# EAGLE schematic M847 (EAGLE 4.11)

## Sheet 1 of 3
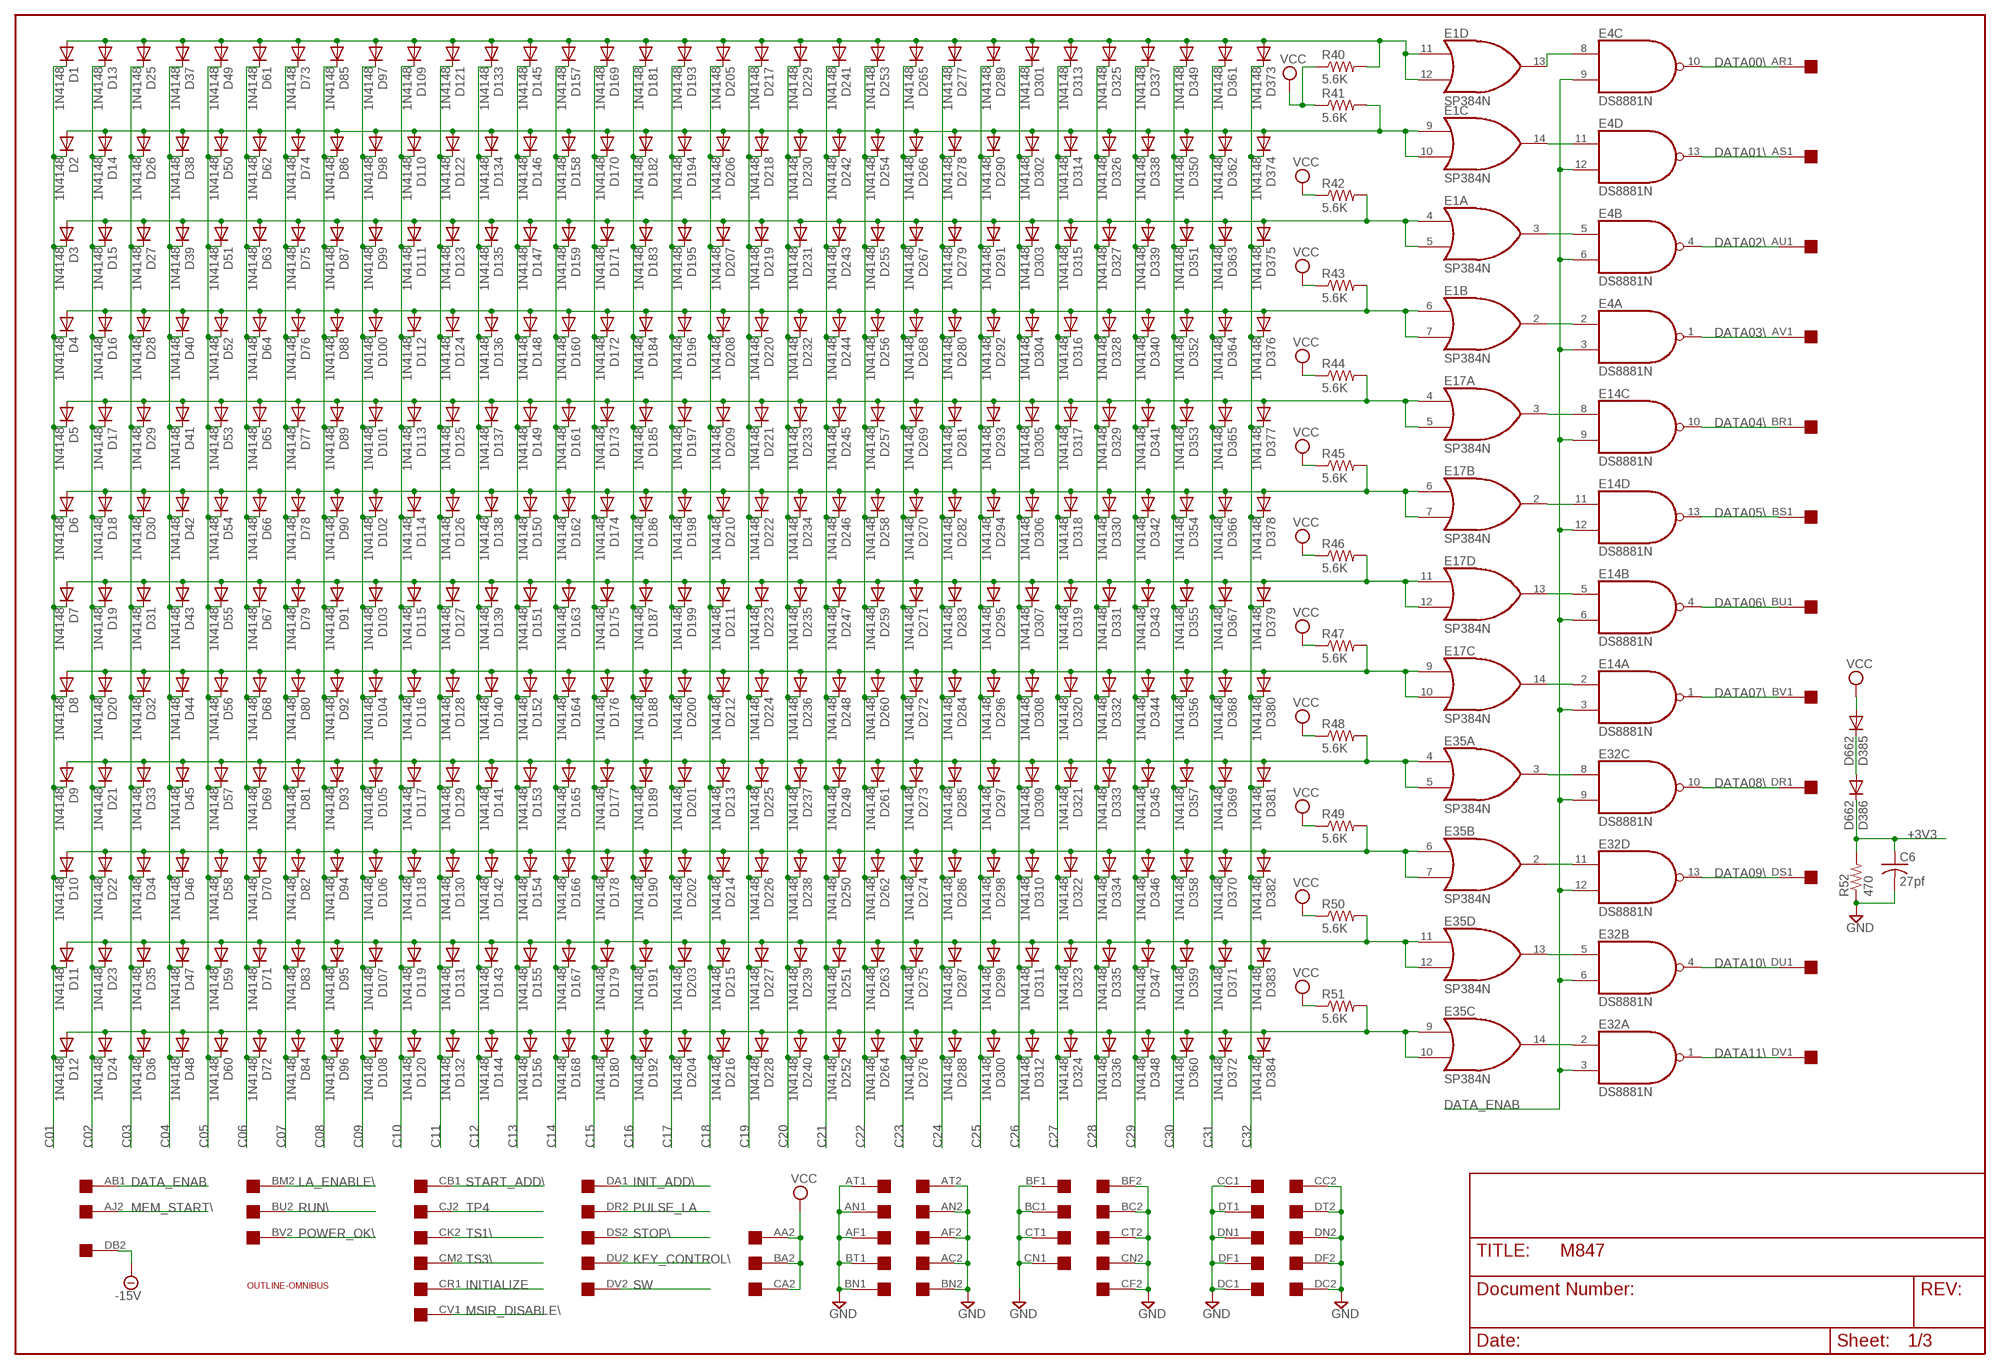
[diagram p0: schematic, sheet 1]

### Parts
C6  27pf  C-US050-025X075  [C050-025X075]
D1  1N4148  [DO35-10]
D2  1N4148  [DO35-10]
D3  1N4148  [DO35-10]
D4  1N4148  [DO35-10]
D5  1N4148  [DO35-10]
D6  1N4148  [DO35-10]
D7  1N4148  [DO35-10]
D8  1N4148  [DO35-10]
D9  1N4148  [DO35-10]
D10  1N4148  [DO35-10]
D11  1N4148  [DO35-10]
D12  1N4148  [DO35-10]
D13  1N4148  [DO35-10]
D14  1N4148  [DO35-10]
D15  1N4148  [DO35-10]
D16  1N4148  [DO35-10]
D17  1N4148  [DO35-10]
D18  1N4148  [DO35-10]
D19  1N4148  [DO35-10]
D20  1N4148  [DO35-10]
D21  1N4148  [DO35-10]
D22  1N4148  [DO35-10]
D23  1N4148  [DO35-10]
D24  1N4148  [DO35-10]
D25  1N4148  [DO35-10]
D26  1N4148  [DO35-10]
D27  1N4148  [DO35-10]
D28  1N4148  [DO35-10]
D29  1N4148  [DO35-10]
D30  1N4148  [DO35-10]
D31  1N4148  [DO35-10]
D32  1N4148  [DO35-10]
D33  1N4148  [DO35-10]
D34  1N4148  [DO35-10]
D35  1N4148  [DO35-10]
D36  1N4148  [DO35-10]
D37  1N4148  [DO35-10]
D38  1N4148  [DO35-10]
D39  1N4148  [DO35-10]
D40  1N4148  [DO35-10]
D41  1N4148  [DO35-10]
D42  1N4148  [DO35-10]
D43  1N4148  [DO35-10]
D44  1N4148  [DO35-10]
D45  1N4148  [DO35-10]
D46  1N4148  [DO35-10]
D47  1N4148  [DO35-10]
D48  1N4148  [DO35-10]
D49  1N4148  [DO35-10]
D50  1N4148  [DO35-10]
D51  1N4148  [DO35-10]
D52  1N4148  [DO35-10]
D53  1N4148  [DO35-10]
D54  1N4148  [DO35-10]
D55  1N4148  [DO35-10]
D56  1N4148  [DO35-10]
D57  1N4148  [DO35-10]
D58  1N4148  [DO35-10]
D59  1N4148  [DO35-10]
D60  1N4148  [DO35-10]
D61  1N4148  [DO35-10]
D62  1N4148  [DO35-10]
D63  1N4148  [DO35-10]
D64  1N4148  [DO35-10]
D65  1N4148  [DO35-10]
D66  1N4148  [DO35-10]
D67  1N4148  [DO35-10]
D68  1N4148  [DO35-10]
D69  1N4148  [DO35-10]
D70  1N4148  [DO35-10]
D71  1N4148  [DO35-10]
D72  1N4148  [DO35-10]
D73  1N4148  [DO35-10]
D74  1N4148  [DO35-10]
D75  1N4148  [DO35-10]
D76  1N4148  [DO35-10]
D77  1N4148  [DO35-10]
D78  1N4148  [DO35-10]
D79  1N4148  [DO35-10]
D80  1N4148  [DO35-10]
D81  1N4148  [DO35-10]
D82  1N4148  [DO35-10]
D83  1N4148  [DO35-10]
D84  1N4148  [DO35-10]
D85  1N4148  [DO35-10]
D86  1N4148  [DO35-10]
D87  1N4148  [DO35-10]
D88  1N4148  [DO35-10]
D89  1N4148  [DO35-10]
D90  1N4148  [DO35-10]
D91  1N4148  [DO35-10]
D92  1N4148  [DO35-10]
D93  1N4148  [DO35-10]
D94  1N4148  [DO35-10]
D95  1N4148  [DO35-10]
D96  1N4148  [DO35-10]
D97  1N4148  [DO35-10]
D98  1N4148  [DO35-10]
D99  1N4148  [DO35-10]
D100  1N4148  [DO35-10]
D101  1N4148  [DO35-10]
D102  1N4148  [DO35-10]
D103  1N4148  [DO35-10]
D104  1N4148  [DO35-10]
D105  1N4148  [DO35-10]
D106  1N4148  [DO35-10]
D107  1N4148  [DO35-10]
D108  1N4148  [DO35-10]
D109  1N4148  [DO35-10]
D110  1N4148  [DO35-10]
D111  1N4148  [DO35-10]
D112  1N4148  [DO35-10]
D113  1N4148  [DO35-10]
D114  1N4148  [DO35-10]
D115  1N4148  [DO35-10]
D116  1N4148  [DO35-10]
D117  1N4148  [DO35-10]
D118  1N4148  [DO35-10]
D119  1N4148  [DO35-10]
D120  1N4148  [DO35-10]
D121  1N4148  [DO35-10]
D122  1N4148  [DO35-10]
D123  1N4148  [DO35-10]
D124  1N4148  [DO35-10]
D125  1N4148  [DO35-10]
D126  1N4148  [DO35-10]
D127  1N4148  [DO35-10]
D128  1N4148  [DO35-10]
D129  1N4148  [DO35-10]
D130  1N4148  [DO35-10]
D131  1N4148  [DO35-10]
D132  1N4148  [DO35-10]
D133  1N4148  [DO35-10]
D134  1N4148  [DO35-10]
D135  1N4148  [DO35-10]
D136  1N4148  [DO35-10]
D137  1N4148  [DO35-10]
D138  1N4148  [DO35-10]
D139  1N4148  [DO35-10]
D140  1N4148  [DO35-10]
D141  1N4148  [DO35-10]
D142  1N4148  [DO35-10]
D143  1N4148  [DO35-10]
D144  1N4148  [DO35-10]
D145  1N4148  [DO35-10]
D146  1N4148  [DO35-10]
D147  1N4148  [DO35-10]
D148  1N4148  [DO35-10]
D149  1N4148  [DO35-10]
D150  1N4148  [DO35-10]
D151  1N4148  [DO35-10]
D152  1N4148  [DO35-10]
D153  1N4148  [DO35-10]
D154  1N4148  [DO35-10]
D155  1N4148  [DO35-10]
D156  1N4148  [DO35-10]
D157  1N4148  [DO35-10]
D158  1N4148  [DO35-10]
D159  1N4148  [DO35-10]
D160  1N4148  [DO35-10]
D161  1N4148  [DO35-10]
D162  1N4148  [DO35-10]
D163  1N4148  [DO35-10]
D164  1N4148  [DO35-10]
D165  1N4148  [DO35-10]
D166  1N4148  [DO35-10]
D167  1N4148  [DO35-10]
D168  1N4148  [DO35-10]
D169  1N4148  [DO35-10]
D170  1N4148  [DO35-10]
D171  1N4148  [DO35-10]
D172  1N4148  [DO35-10]
D173  1N4148  [DO35-10]
D174  1N4148  [DO35-10]
D175  1N4148  [DO35-10]
D176  1N4148  [DO35-10]
D177  1N4148  [DO35-10]
D178  1N4148  [DO35-10]
D179  1N4148  [DO35-10]
D180  1N4148  [DO35-10]
D181  1N4148  [DO35-10]
D182  1N4148  [DO35-10]
D183  1N4148  [DO35-10]
D184  1N4148  [DO35-10]
D185  1N4148  [DO35-10]
D186  1N4148  [DO35-10]
D187  1N4148  [DO35-10]
D188  1N4148  [DO35-10]
D189  1N4148  [DO35-10]
D190  1N4148  [DO35-10]
D191  1N4148  [DO35-10]
D192  1N4148  [DO35-10]
D193  1N4148  [DO35-10]
D194  1N4148  [DO35-10]
D195  1N4148  [DO35-10]
D196  1N4148  [DO35-10]
D197  1N4148  [DO35-10]
D198  1N4148  [DO35-10]
D199  1N4148  [DO35-10]
D200  1N4148  [DO35-10]
D201  1N4148  [DO35-10]
D202  1N4148  [DO35-10]
D203  1N4148  [DO35-10]
D204  1N4148  [DO35-10]
D205  1N4148  [DO35-10]
D206  1N4148  [DO35-10]
D207  1N4148  [DO35-10]
D208  1N4148  [DO35-10]
D209  1N4148  [DO35-10]
D210  1N4148  [DO35-10]
D211  1N4148  [DO35-10]
D212  1N4148  [DO35-10]
D213  1N4148  [DO35-10]
D214  1N4148  [DO35-10]
D215  1N4148  [DO35-10]
D216  1N4148  [DO35-10]
D217  1N4148  [DO35-10]
D218  1N4148  [DO35-10]
D219  1N4148  [DO35-10]
D220  1N4148  [DO35-10]
D221  1N4148  [DO35-10]
D222  1N4148  [DO35-10]
D223  1N4148  [DO35-10]
D224  1N4148  [DO35-10]
D225  1N4148  [DO35-10]
D226  1N4148  [DO35-10]
D227  1N4148  [DO35-10]
D228  1N4148  [DO35-10]
D229  1N4148  [DO35-10]
D230  1N4148  [DO35-10]
D231  1N4148  [DO35-10]
D232  1N4148  [DO35-10]
D233  1N4148  [DO35-10]
D234  1N4148  [DO35-10]
D235  1N4148  [DO35-10]
D236  1N4148  [DO35-10]
D237  1N4148  [DO35-10]
D238  1N4148  [DO35-10]
D239  1N4148  [DO35-10]
D240  1N4148  [DO35-10]
D241  1N4148  [DO35-10]
D242  1N4148  [DO35-10]
D243  1N4148  [DO35-10]
D244  1N4148  [DO35-10]
D245  1N4148  [DO35-10]
D246  1N4148  [DO35-10]
D247  1N4148  [DO35-10]
D248  1N4148  [DO35-10]
D249  1N4148  [DO35-10]
D250  1N4148  [DO35-10]
D251  1N4148  [DO35-10]
D252  1N4148  [DO35-10]
D253  1N4148  [DO35-10]
D254  1N4148  [DO35-10]
D255  1N4148  [DO35-10]
D256  1N4148  [DO35-10]
D257  1N4148  [DO35-10]
D258  1N4148  [DO35-10]
D259  1N4148  [DO35-10]
D260  1N4148  [DO35-10]
D261  1N4148  [DO35-10]
D262  1N4148  [DO35-10]
D263  1N4148  [DO35-10]
D264  1N4148  [DO35-10]
D265  1N4148  [DO35-10]
D266  1N4148  [DO35-10]
D267  1N4148  [DO35-10]
D268  1N4148  [DO35-10]
D269  1N4148  [DO35-10]
D270  1N4148  [DO35-10]
D271  1N4148  [DO35-10]
D272  1N4148  [DO35-10]
D273  1N4148  [DO35-10]
D274  1N4148  [DO35-10]
D275  1N4148  [DO35-10]
D276  1N4148  [DO35-10]
D277  1N4148  [DO35-10]
D278  1N4148  [DO35-10]
D279  1N4148  [DO35-10]
D280  1N4148  [DO35-10]
D281  1N4148  [DO35-10]
D282  1N4148  [DO35-10]
D283  1N4148  [DO35-10]
D284  1N4148  [DO35-10]
D285  1N4148  [DO35-10]
D286  1N4148  [DO35-10]
D287  1N4148  [DO35-10]
D288  1N4148  [DO35-10]
D289  1N4148  [DO35-10]
D290  1N4148  [DO35-10]
D291  1N4148  [DO35-10]
D292  1N4148  [DO35-10]
D293  1N4148  [DO35-10]
D294  1N4148  [DO35-10]
D295  1N4148  [DO35-10]
D296  1N4148  [DO35-10]
D297  1N4148  [DO35-10]
D298  1N4148  [DO35-10]
D299  1N4148  [DO35-10]
D300  1N4148  [DO35-10]
D301  1N4148  [DO35-10]
D302  1N4148  [DO35-10]
D303  1N4148  [DO35-10]
D304  1N4148  [DO35-10]
D305  1N4148  [DO35-10]
D306  1N4148  [DO35-10]
D307  1N4148  [DO35-10]
D308  1N4148  [DO35-10]
D309  1N4148  [DO35-10]
D310  1N4148  [DO35-10]
D311  1N4148  [DO35-10]
D312  1N4148  [DO35-10]
D313  1N4148  [DO35-10]
D314  1N4148  [DO35-10]
D315  1N4148  [DO35-10]
D316  1N4148  [DO35-10]
D317  1N4148  [DO35-10]
D318  1N4148  [DO35-10]
D319  1N4148  [DO35-10]
D320  1N4148  [DO35-10]
D321  1N4148  [DO35-10]
D322  1N4148  [DO35-10]
D323  1N4148  [DO35-10]
D324  1N4148  [DO35-10]
D325  1N4148  [DO35-10]
D326  1N4148  [DO35-10]
D327  1N4148  [DO35-10]
D328  1N4148  [DO35-10]
D329  1N4148  [DO35-10]
D330  1N4148  [DO35-10]
D331  1N4148  [DO35-10]
D332  1N4148  [DO35-10]
D333  1N4148  [DO35-10]
D334  1N4148  [DO35-10]
D335  1N4148  [DO35-10]
D336  1N4148  [DO35-10]
D337  1N4148  [DO35-10]
D338  1N4148  [DO35-10]
D339  1N4148  [DO35-10]
D340  1N4148  [DO35-10]
D341  1N4148  [DO35-10]
D342  1N4148  [DO35-10]
D343  1N4148  [DO35-10]
D344  1N4148  [DO35-10]
D345  1N4148  [DO35-10]
D346  1N4148  [DO35-10]
D347  1N4148  [DO35-10]
D348  1N4148  [DO35-10]
D349  1N4148  [DO35-10]
D350  1N4148  [DO35-10]
D351  1N4148  [DO35-10]
D352  1N4148  [DO35-10]
D353  1N4148  [DO35-10]
D354  1N4148  [DO35-10]
D355  1N4148  [DO35-10]
D356  1N4148  [DO35-10]
D357  1N4148  [DO35-10]
D358  1N4148  [DO35-10]
D359  1N4148  [DO35-10]
D360  1N4148  [DO35-10]
D361  1N4148  [DO35-10]
D362  1N4148  [DO35-10]
D363  1N4148  [DO35-10]
D364  1N4148  [DO35-10]
D365  1N4148  [DO35-10]
D366  1N4148  [DO35-10]
D367  1N4148  [DO35-10]
D368  1N4148  [DO35-10]
D369  1N4148  [DO35-10]
D370  1N4148  [DO35-10]
D371  1N4148  [DO35-10]
D372  1N4148  [DO35-10]
D373  1N4148  [DO35-10]
D374  1N4148  [DO35-10]
D375  1N4148  [DO35-10]
D376  1N4148  [DO35-10]
D377  1N4148  [DO35-10]
D378  1N4148  [DO35-10]
D379  1N4148  [DO35-10]
D380  1N4148  [DO35-10]
D381  1N4148  [DO35-10]
D382  1N4148  [DO35-10]
D383  1N4148  [DO35-10]
D384  1N4148  [DO35-10]
D385  D662  1N4148  [DO35-10]
D386  D662  1N4148  [DO35-10]
E1  SP384N  [DIL14]
E4  DS8881N  [DIL14]
E14  DS8881N  [DIL14]
E17  SP384N  [DIL14]
E32  DS8881N  [DIL14]
E35  SP384N  [DIL14]
R40  5.6K  R-US_0207/10  [0207/10]
R41  5.6K  R-US_0207/10  [0207/10]
R42  5.6K  R-US_0207/10  [0207/10]
R43  5.6K  R-US_0207/10  [0207/10]
R44  5.6K  R-US_0207/10  [0207/10]
R45  5.6K  R-US_0207/10  [0207/10]
R46  5.6K  R-US_0207/10  [0207/10]
R47  5.6K  R-US_0207/10  [0207/10]
R48  5.6K  R-US_0207/10  [0207/10]
R49  5.6K  R-US_0207/10  [0207/10]
R50  5.6K  R-US_0207/10  [0207/10]
R51  5.6K  R-US_0207/10  [0207/10]
R52  470  R-US_0207/10  [0207/10]
U$1  OUTLINE-OMNIBUS  [OMNIBUS]
U$2  QUAD  [EDGE-CON8]

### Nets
+3V3 [supply]: C6.1 D386.C R52.2 ; also sheet 2,3
-15V [supply]: U$2.DB2 ; also sheet 2,3
C01: D1.C D2.C D3.C D4.C D5.C D6.C D7.C D8.C D9.C D10.C D11.C D12.C ; also sheet 2
C02: D13.C D14.C D15.C D16.C D17.C D18.C D19.C D20.C D21.C D22.C D23.C D24.C ; also sheet 2
C03: D25.C D26.C D27.C D28.C D29.C D30.C D31.C D32.C D33.C D34.C D35.C D36.C ; also sheet 2
C04: D37.C D38.C D39.C D40.C D41.C D42.C D43.C D44.C D45.C D46.C D47.C D48.C ; also sheet 2
C05: D49.C D50.C D51.C D52.C D53.C D54.C D55.C D56.C D57.C D58.C D59.C D60.C ; also sheet 2
C06: D61.C D62.C D63.C D64.C D65.C D66.C D67.C D68.C D69.C D70.C D71.C D72.C ; also sheet 2
C07: D73.C D74.C D75.C D76.C D77.C D78.C D79.C D80.C D81.C D82.C D83.C D84.C ; also sheet 2
C08: D85.C D86.C D87.C D88.C D89.C D90.C D91.C D92.C D93.C D94.C D95.C D96.C ; also sheet 2
C09: D97.C D98.C D99.C D100.C D101.C D102.C D103.C D104.C D105.C D106.C D107.C D108.C ; also sheet 2
C10: D109.C D110.C D111.C D112.C D113.C D114.C D115.C D116.C D117.C D118.C D119.C D120.C ; also sheet 2
C11: D121.C D122.C D123.C D124.C D125.C D126.C D127.C D128.C D129.C D130.C D131.C D132.C ; also sheet 2
C12: D133.C D134.C D135.C D136.C D137.C D138.C D139.C D140.C D141.C D142.C D143.C D144.C ; also sheet 2
C13: D145.C D146.C D147.C D148.C D149.C D150.C D151.C D152.C D153.C D154.C D155.C D156.C ; also sheet 2
C14: D157.C D158.C D159.C D160.C D161.C D162.C D163.C D164.C D165.C D166.C D167.C D168.C ; also sheet 2
C15: D169.C D170.C D171.C D172.C D173.C D174.C D175.C D176.C D177.C D178.C D179.C D180.C ; also sheet 2
C16: D181.C D182.C D183.C D184.C D185.C D186.C D187.C D188.C D189.C D190.C D191.C D192.C ; also sheet 2
C17: D193.C D194.C D195.C D196.C D197.C D198.C D199.C D200.C D201.C D202.C D203.C D204.C ; also sheet 2
C18: D205.C D206.C D207.C D208.C D209.C D210.C D211.C D212.C D213.C D214.C D215.C D216.C ; also sheet 2
C19: D217.C D218.C D219.C D220.C D221.C D222.C D223.C D224.C D225.C D226.C D227.C D228.C ; also sheet 2
C20: D229.C D230.C D231.C D232.C D233.C D234.C D235.C D236.C D237.C D238.C D239.C D240.C ; also sheet 2
C21: D241.C D242.C D243.C D244.C D245.C D246.C D247.C D248.C D249.C D250.C D251.C D252.C ; also sheet 2
C22: D253.C D254.C D255.C D256.C D257.C D258.C D259.C D260.C D261.C D262.C D263.C D264.C ; also sheet 2
C23: D265.C D266.C D267.C D268.C D269.C D270.C D271.C D272.C D273.C D274.C D275.C D276.C ; also sheet 2
C24: D277.C D278.C D279.C D280.C D281.C D282.C D283.C D284.C D285.C D286.C D287.C D288.C ; also sheet 2
C25: D289.C D290.C D291.C D292.C D293.C D294.C D295.C D296.C D297.C D298.C D299.C D300.C ; also sheet 2
C26: D301.C D302.C D303.C D304.C D305.C D306.C D307.C D308.C D309.C D310.C D311.C D312.C ; also sheet 2
C27: D313.C D314.C D315.C D316.C D317.C D318.C D319.C D320.C D321.C D322.C D323.C D324.C ; also sheet 2
C28: D325.C D326.C D327.C D328.C D329.C D330.C D331.C D332.C D333.C D334.C D335.C D336.C ; also sheet 2
C29: D337.C D338.C D339.C D340.C D341.C D342.C D343.C D344.C D345.C D346.C D347.C D348.C ; also sheet 2
C30: D349.C D350.C D351.C D352.C D353.C D354.C D355.C D356.C D357.C D358.C D359.C D360.C ; also sheet 2
C31: D361.C D362.C D363.C D364.C D365.C D366.C D367.C D368.C D369.C D370.C D371.C D372.C ; also sheet 2
C32: D373.C D374.C D375.C D376.C D377.C D378.C D379.C D380.C D381.C D382.C D383.C D384.C ; also sheet 2
DATA00\: E4.10(C:O) U$2.AR1 ; also sheet 2
DATA01\: E4.13(D:O) U$2.AS1 ; also sheet 2
DATA02\: E4.4(B:O) U$2.AU1 ; also sheet 2
DATA03\: E4.1(A:O) U$2.AV1 ; also sheet 2
DATA04\: E14.10(C:O) U$2.BR1 ; also sheet 2
DATA05\: E14.13(D:O) U$2.BS1 ; also sheet 2
DATA06\: E14.4(B:O) U$2.BU1 ; also sheet 2
DATA07\: E14.1(A:O) U$2.BV1 ; also sheet 2
DATA08\: E32.10(C:O) U$2.DR1 ; also sheet 2
DATA09\: E32.13(D:O) U$2.DS1 ; also sheet 2
DATA10\: E32.4(B:O) U$2.DU1 ; also sheet 2
DATA11\: E32.1(A:O) U$2.DV1 ; also sheet 2
DATA_ENAB: E4.3(A:I1) E4.6(B:I1) E4.9(C:I1) E4.12(D:I1) E14.3(A:I1) E14.6(B:I1) E14.9(C:I1) E14.12(D:I1) E32.3(A:I1) E32.6(B:I1) E32.9(C:I1) E32.12(D:I1) U$2.AB1 ; also sheet 3
GND [supply]: C6.2 R52.1 U$2.AC2 U$2.AF1 U$2.AF2 U$2.AN1 U$2.AN2 U$2.AT1 U$2.AT2 U$2.BC1 U$2.BC2 U$2.BF1 U$2.BF2 U$2.BN1 U$2.BN2 U$2.BT1 U$2.CC1 U$2.CC2 U$2.CF2 U$2.CN1 U$2.CN2 U$2.CT1 U$2.CT2 U$2.DC1 U$2.DC2 U$2.DF1 U$2.DF2 U$2.DN1 U$2.DN2 U$2.DT1 U$2.DT2 ; also sheet 2,3
INIT_ADD\: U$2.DA1 ; also sheet 2,3
INITIALIZE: U$2.CR1 ; also sheet 3
KEY_CONTROL\: U$2.DU2 ; also sheet 2
LA_ENABLE\: U$2.BM2 ; also sheet 2
MEM_START\: U$2.AJ2 ; also sheet 2
MSIR_DISABLE\: U$2.CV1 ; also sheet 3
N$33: D1.A D13.A D25.A D37.A D49.A D61.A D73.A D85.A D97.A D109.A D121.A D133.A D145.A D157.A D169.A D181.A D193.A D205.A D217.A D229.A D241.A D253.A D265.A D277.A D289.A D301.A D313.A D325.A D337.A D349.A D361.A D373.A E1.11(D:I0) E1.12(D:I1) R40.2
N$34: D12.A D24.A D36.A D48.A D60.A D72.A D84.A D96.A D108.A D120.A D132.A D144.A D156.A D168.A D180.A D192.A D204.A D216.A D228.A D240.A D252.A D264.A D276.A D288.A D300.A D312.A D324.A D336.A D348.A D360.A D372.A D384.A E35.9(C:I0) E35.10(C:I1) R51.2
N$35: D11.A D23.A D35.A D47.A D59.A D71.A D83.A D95.A D107.A D119.A D131.A D143.A D155.A D167.A D179.A D191.A D203.A D215.A D227.A D239.A D251.A D263.A D275.A D287.A D299.A D311.A D323.A D335.A D347.A D359.A D371.A D383.A E35.11(D:I0) E35.12(D:I1) R50.2
N$36: D10.A D22.A D34.A D46.A D58.A D70.A D82.A D94.A D106.A D118.A D130.A D142.A D154.A D166.A D178.A D190.A D202.A D214.A D226.A D238.A D250.A D262.A D274.A D286.A D298.A D310.A D322.A D334.A D346.A D358.A D370.A D382.A E35.6(B:I0) E35.7(B:I1) R49.2
N$37: D8.A D20.A D32.A D44.A D56.A D68.A D80.A D92.A D104.A D116.A D128.A D140.A D152.A D164.A D176.A D188.A D200.A D212.A D224.A D236.A D248.A D260.A D272.A D284.A D296.A D308.A D320.A D332.A D344.A D356.A D368.A D380.A E17.9(C:I0) E17.10(C:I1) R47.2
N$38: D7.A D19.A D31.A D43.A D55.A D67.A D79.A D91.A D103.A D115.A D127.A D139.A D151.A D163.A D175.A D187.A D199.A D211.A D223.A D235.A D247.A D259.A D271.A D283.A D295.A D307.A D319.A D331.A D343.A D355.A D367.A D379.A E17.11(D:I0) E17.12(D:I1) R46.2
N$39: D9.A D21.A D33.A D45.A D57.A D69.A D81.A D93.A D105.A D117.A D129.A D141.A D153.A D165.A D177.A D189.A D201.A D213.A D225.A D237.A D249.A D261.A D273.A D285.A D297.A D309.A D321.A D333.A D345.A D357.A D369.A D381.A E35.4(A:I0) E35.5(A:I1) R48.2
N$40: D6.A D18.A D30.A D42.A D54.A D66.A D78.A D90.A D102.A D114.A D126.A D138.A D150.A D162.A D174.A D186.A D198.A D210.A D222.A D234.A D246.A D258.A D270.A D282.A D294.A D306.A D318.A D330.A D342.A D354.A D366.A D378.A E17.6(B:I0) E17.7(B:I1) R45.2
N$41: D5.A D17.A D29.A D41.A D53.A D65.A D77.A D89.A D101.A D113.A D125.A D137.A D149.A D161.A D173.A D185.A D197.A D209.A D221.A D233.A D245.A D257.A D269.A D281.A D293.A D305.A D317.A D329.A D341.A D353.A D365.A D377.A E17.4(A:I0) E17.5(A:I1) R44.2
N$42: D4.A D16.A D28.A D40.A D52.A D64.A D76.A D88.A D100.A D112.A D124.A D136.A D148.A D160.A D172.A D184.A D196.A D208.A D220.A D232.A D244.A D256.A D268.A D280.A D292.A D304.A D316.A D328.A D340.A D352.A D364.A D376.A E1.6(B:I0) E1.7(B:I1) R43.2
N$43: D3.A D15.A D27.A D39.A D51.A D63.A D75.A D87.A D99.A D111.A D123.A D135.A D147.A D159.A D171.A D183.A D195.A D207.A D219.A D231.A D243.A D255.A D267.A D279.A D291.A D303.A D315.A D327.A D339.A D351.A D363.A D375.A E1.4(A:I0) E1.5(A:I1) R42.2
N$44: D2.A D14.A D26.A D38.A D50.A D62.A D74.A D86.A D98.A D110.A D122.A D134.A D146.A D158.A D170.A D182.A D194.A D206.A D218.A D230.A D242.A D254.A D266.A D278.A D290.A D302.A D314.A D326.A D338.A D350.A D362.A D374.A E1.9(C:I0) E1.10(C:I1) R41.2
N$45: E14.5(B:I0) E17.13(D:O)
N$46: E14.11(D:I0) E17.2(B:O)
N$47: E14.8(C:I0) E17.3(A:O)
N$48: E1.2(B:O) E4.2(A:I0)
N$49: E1.3(A:O) E4.5(B:I0)
N$50: E1.14(C:O) E4.11(D:I0)
N$51: E1.13(D:O) E4.8(C:I0)
N$52: E32.2(A:I0) E35.14(C:O)
N$53: E32.5(B:I0) E35.13(D:O)
N$54: E32.11(D:I0) E35.2(B:O)
N$55: E32.8(C:I0) E35.3(A:O)
N$56: E14.2(A:I0) E17.14(C:O)
N$142: D385.C D386.A
POWER_OK\: U$2.BV2 ; also sheet 3
PULSE_LA: U$2.DR2 ; also sheet 2
RUN\: U$2.BU2 ; also sheet 3
START_ADD\: U$2.CB1 ; also sheet 2,3
STOP\: U$2.DS2 ; also sheet 3
SW: U$2.DV2 ; also sheet 3
TP4: U$2.CJ2 ; also sheet 3
TS1\: U$2.CK2 ; also sheet 2
TS3\: U$2.CM2 ; also sheet 2
VCC [supply]: D385.A R40.1 R41.1 R42.1 R43.1 R44.1 R45.1 R46.1 R47.1 R48.1 R49.1 R50.1 R51.1 U$2.AA2 U$2.BA2 U$2.CA2 ; also sheet 2,3
Unconnected: U$2.AA1 U$2.AB2 U$2.AC1 U$2.AD1 U$2.AD2 U$2.AE1 U$2.AE2 U$2.AH1 U$2.AH2 U$2.AJ1 U$2.AK1 U$2.AK2 U$2.AL1 U$2.AL2 U$2.AM1 U$2.AM2 U$2.AP1 U$2.AP2 U$2.AR2 U$2.AS2 U$2.AU2 U$2.AV2 U$2.BA1 U$2.BB1 U$2.BB2 U$2.BD1 U$2.BD2 U$2.BE1 U$2.BE2 U$2.BH1 U$2.BH2 U$2.BJ1 U$2.BJ2 U$2.BK1 U$2.BK2 U$2.BL1 U$2.BL2 U$2.BM1 U$2.BP1 U$2.BP2 U$2.BR2 U$2.BS2 U$2.BT2 U$2.CA1 U$2.CB2 U$2.CD1 U$2.CD2 U$2.CE1 U$2.CE2 U$2.CF1 U$2.CH1 U$2.CH2 U$2.CJ1 U$2.CK1 U$2.CL1 U$2.CL2 U$2.CM1 U$2.CP1 U$2.CP2 U$2.CR2 U$2.CS1 U$2.CS2 U$2.CU1 U$2.CU2 U$2.CV2 U$2.DA2 U$2.DB1 U$2.DD1 U$2.DD2 U$2.DE1 U$2.DE2 U$2.DH1 U$2.DH2 U$2.DJ1 U$2.DJ2 U$2.DK1 U$2.DK2 U$2.DL1 U$2.DL2 U$2.DM1 U$2.DM2 U$2.DP1 U$2.DP2

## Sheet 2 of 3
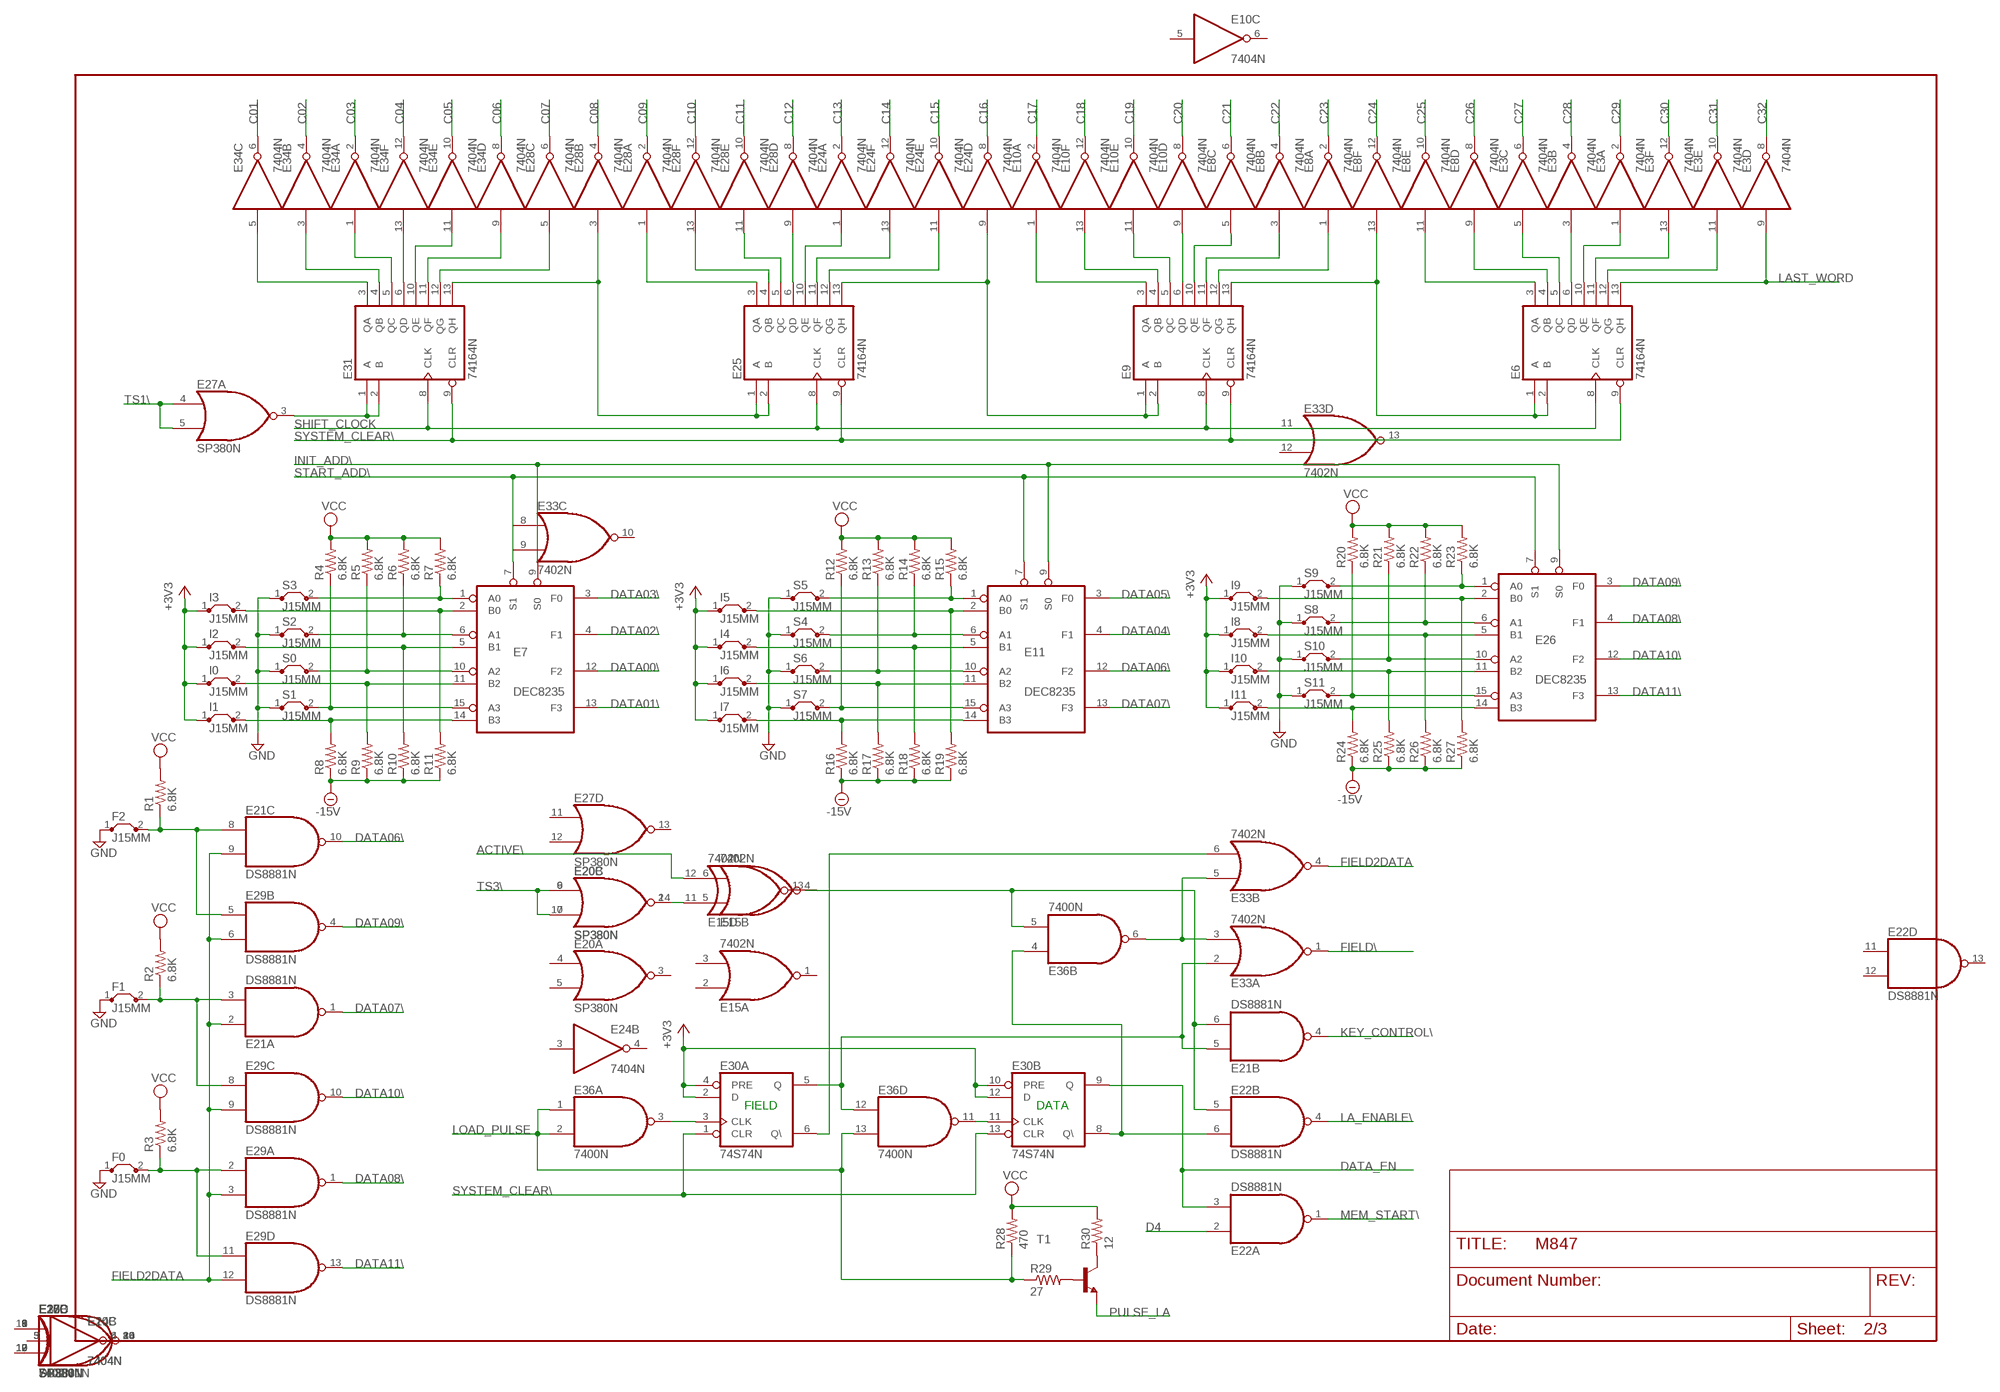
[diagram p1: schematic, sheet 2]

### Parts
E3  7404N  [DIL14]
E6  74164N  [DIL14]
E7  DEC8235  [DIL16]
E8  7404N  [DIL14]
E9  74164N  [DIL14]
E10  7404N  [DIL14]
E11  DEC8235  [DIL16]
E15  7402N  [DIL14]
E20  SP380N  [DIL14]
E21  DS8881N  [DIL14]
E22  DS8881N  [DIL14]
E24  7404N  [DIL14]
E25  74164N  [DIL14]
E26  DEC8235  [DIL16]
E27  SP380N  [DIL14]
E28  7404N  [DIL14]
E29  DS8881N  [DIL14]
E30  74S74N  [DIL14]
E31  74164N  [DIL14]
E33  7402N  [DIL14]
E34  7404N  [DIL14]
E36  7400N  [DIL14]
F0  J15MM  [15]
F1  J15MM  [15]
F2  J15MM  [15]
I0  J15MM  [15]
I1  J15MM  [15]
I2  J15MM  [15]
I3  J15MM  [15]
I4  J15MM  [15]
I5  J15MM  [15]
I6  J15MM  [15]
I7  J15MM  [15]
I8  J15MM  [15]
I9  J15MM  [15]
I10  J15MM  [15]
I11  J15MM  [15]
R1  6.8K  R-US_0207/10  [0207/10]
R2  6.8K  R-US_0207/10  [0207/10]
R3  6.8K  R-US_0207/10  [0207/10]
R4  6.8K  R-US_0207/10  [0207/10]
R5  6.8K  R-US_0207/10  [0207/10]
R6  6.8K  R-US_0207/10  [0207/10]
R7  6.8K  R-US_0207/10  [0207/10]
R8  6.8K  R-US_0207/10  [0207/10]
R9  6.8K  R-US_0207/10  [0207/10]
R10  6.8K  R-US_0207/10  [0207/10]
R11  6.8K  R-US_0207/10  [0207/10]
R12  6.8K  R-US_0207/10  [0207/10]
R13  6.8K  R-US_0207/10  [0207/10]
R14  6.8K  R-US_0207/10  [0207/10]
R15  6.8K  R-US_0207/10  [0207/10]
R16  6.8K  R-US_0207/10  [0207/10]
R17  6.8K  R-US_0207/10  [0207/10]
R18  6.8K  R-US_0207/10  [0207/10]
R19  6.8K  R-US_0207/10  [0207/10]
R20  6.8K  R-US_0207/10  [0207/10]
R21  6.8K  R-US_0207/10  [0207/10]
R22  6.8K  R-US_0207/10  [0207/10]
R23  6.8K  R-US_0207/10  [0207/10]
R24  6.8K  R-US_0207/10  [0207/10]
R25  6.8K  R-US_0207/10  [0207/10]
R26  6.8K  R-US_0207/10  [0207/10]
R27  6.8K  R-US_0207/10  [0207/10]
R28  470  R-US_0207/10  [0207/10]
R29  27  R-US_0207/10  [0207/10]
R30  12  R-US_0207/10  [0207/10]
S0  J15MM  [15]
S1  J15MM  [15]
S2  J15MM  [15]
S3  J15MM  [15]
S4  J15MM  [15]
S5  J15MM  [15]
S6  J15MM  [15]
S7  J15MM  [15]
S8  J15MM  [15]
S9  J15MM  [15]
S10  J15MM  [15]
S11  J15MM  [15]
T1  -NPN-TO92  [TO92]

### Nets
+3V3 [supply]: E30.2(A:D) E30.4(A:PRE) E30.10(B:PRE) E30.12(B:D) I0.1 I1.1 I2.1 I3.1 I4.1 I5.1 I6.1 I7.1 I8.1 I9.1 I10.1 I11.1 ; also sheet 1,3
-15V [supply]: R8.1 R9.1 R10.1 R11.1 R16.1 R17.1 R18.1 R19.1 R24.1 R25.1 R26.1 R27.1 ; also sheet 1,3
ACTIVE\: E15.12(D:I1) ; also sheet 3
C01: E34.6(C:O) ; also sheet 1
C02: E34.4(B:O) ; also sheet 1
C03: E34.2(A:O) ; also sheet 1
C04: E34.12(F:O) ; also sheet 1
C05: E34.10(E:O) ; also sheet 1
C06: E34.8(D:O) ; also sheet 1
C07: E28.6(C:O) ; also sheet 1
C08: E28.4(B:O) ; also sheet 1
C09: E28.2(A:O) ; also sheet 1
C10: E28.12(F:O) ; also sheet 1
C11: E28.10(E:O) ; also sheet 1
C12: E28.8(D:O) ; also sheet 1
C13: E24.2(A:O) ; also sheet 1
C14: E24.12(F:O) ; also sheet 1
C15: E24.10(E:O) ; also sheet 1
C16: E24.8(D:O) ; also sheet 1
C17: E10.2(A:O) ; also sheet 1
C18: E10.12(F:O) ; also sheet 1
C19: E10.10(E:O) ; also sheet 1
C20: E10.8(D:O) ; also sheet 1
C21: E8.6(C:O) ; also sheet 1
C22: E8.4(B:O) ; also sheet 1
C23: E8.2(A:O) ; also sheet 1
C24: E8.12(F:O) ; also sheet 1
C25: E8.10(E:O) ; also sheet 1
C26: E8.8(D:O) ; also sheet 1
C27: E3.6(C:O) ; also sheet 1
C28: E3.4(B:O) ; also sheet 1
C29: E3.2(A:O) ; also sheet 1
C30: E3.12(F:O) ; also sheet 1
C31: E3.10(E:O) ; also sheet 1
C32: E3.8(D:O) ; also sheet 1
D4: E22.2(A:I0) ; also sheet 3
DATA00\: E7.12(F2) ; also sheet 1
DATA01\: E7.13(F3) ; also sheet 1
DATA02\: E7.4(F1) ; also sheet 1
DATA03\: E7.3(F0) ; also sheet 1
DATA04\: E11.4(F1) ; also sheet 1
DATA05\: E11.3(F0) ; also sheet 1
DATA06\: E11.12(F2) E21.10(C:O) ; also sheet 1
DATA07\: E11.13(F3) E21.1(A:O) ; also sheet 1
DATA08\: E26.4(F1) E29.1(A:O) ; also sheet 1
DATA09\: E26.3(F0) E29.4(B:O) ; also sheet 1
DATA10\: E26.12(F2) E29.10(C:O) ; also sheet 1
DATA11\: E26.13(F3) E29.13(D:O) ; also sheet 1
DATA_EN: E22.3(A:I1) E30.9(B:Q) ; also sheet 3
FIELD2DATA: E21.2(A:I0) E21.9(C:I1) E29.3(A:I1) E29.6(B:I1) E29.9(C:I1) E29.12(D:I1) E33.4(B:O)
FIELD\: E33.1(A:O) ; also sheet 3
GND [supply]: F0.1 F1.1 F2.1 S0.1 S1.1 S2.1 S3.1 S4.1 S5.1 S6.1 S7.1 S8.1 S9.1 S10.1 S11.1 ; also sheet 1,3
INIT_ADD\: E7.9(S0) E11.9(S0) E26.9(S0) ; also sheet 1,3
KEY_CONTROL\: E21.4(B:O) ; also sheet 1
LA_ENABLE\: E22.4(B:O) ; also sheet 1
LAST_WORD: E3.9(D:I) E6.13(QH) ; also sheet 3
LOAD_PULSE: E36.1(A:I0) E36.2(A:I1) E36.13(D:I1) R28.1 R29.1 ; also sheet 3
MEM_START\: E22.1(A:O) ; also sheet 1
N$1: E27.3(A:O) E31.1(A) E31.2(B)
N$2: E7.1(A0) R7.1 S3.2
N$3: E21.8(C:I0) E29.5(B:I0) F2.2 R1.1
N$4: E21.3(A:I1) E29.8(C:I0) F1.2 R2.1
N$5: E29.2(A:I0) E29.11(D:I0) F0.2 R3.1
N$6: E7.6(A1) R6.1 S2.2
N$7: E7.10(A2) R5.1 S0.2
N$8: E7.15(A3) R4.1 S1.2
N$9: E7.14(B3) I1.2 R8.2
N$10: E7.11(B2) I0.2 R9.2
N$11: E7.5(B1) I2.2 R10.2
N$12: E7.2(B0) I3.2 R11.2
N$13: E21.5(B:I0) E30.5(A:Q) E33.2(A:I0) E36.12(D:I0)
N$14: E11.1(A0) R15.1 S5.2
N$15: E11.6(A1) R14.1 S4.2
N$16: E11.10(A2) R13.1 S6.2
N$17: E11.15(A3) R12.1 S7.2
N$18: E11.14(B3) I7.2 R16.2
N$19: E11.11(B2) I6.2 R17.2
N$20: E11.5(B1) I4.2 R18.2
N$21: E11.2(B0) I5.2 R19.2
N$22: E30.6(A:Q\) E33.6(B:I1)
N$23: E26.1(A0) R23.1 S9.2
N$24: E26.6(A1) R22.1 S8.2
N$25: E26.10(A2) R21.1 S10.2
N$26: E26.15(A3) R20.1 S11.2
N$27: E26.14(B3) I11.2 R24.2
N$28: E26.11(B2) I10.2 R25.2
N$29: E26.5(B1) I8.2 R26.2
N$30: E26.2(B0) I9.2 R27.2
N$31: R30.1 T1.3(C)
N$32: E31.3(QA) E34.5(C:I)
N$57: R29.2 T1.2(B)
N$58: E30.11(B:CLK) E36.11(D:O)
N$59: E30.3(A:CLK) E36.3(A:O)
N$62: E22.6(B:I1) E30.8(B:Q\) E36.4(B:I0)
N$63: E15.13(D:O) E21.6(B:I1) E22.5(B:I0) E36.5(B:I1)
N$69: E31.6(QD) E34.13(F:I)
N$70: E9.5(QC) E10.11(E:I)
N$71: E9.6(QD) E10.9(D:I)
N$72: E3.3(B:I) E6.6(QD)
N$73: E31.4(QB) E34.3(B:I)
N$74: E31.5(QC) E34.1(A:I)
N$75: E31.10(QE) E34.11(E:I)
N$76: E31.11(QF) E34.9(D:I)
N$77: E28.5(C:I) E31.12(QG)
N$78: E25.3(QA) E28.1(A:I)
N$79: E25.4(QB) E28.13(F:I)
N$80: E25.5(QC) E28.11(E:I)
N$81: E25.6(QD) E28.9(D:I)
N$82: E24.1(A:I) E25.10(QE)
N$83: E9.3(QA) E10.1(A:I)
N$84: E6.3(QA) E8.11(E:I)
N$85: E3.11(E:I) E6.12(QG)
N$86: E3.13(F:I) E6.11(QF)
N$87: E3.1(A:I) E6.10(QE)
N$88: E24.13(F:I) E25.11(QF)
N$89: E24.11(E:I) E25.12(QG)
N$90: E9.4(QB) E10.13(F:I)
N$91: E8.5(C:I) E9.10(QE)
N$92: E8.3(B:I) E9.11(QF)
N$93: E8.1(A:I) E9.12(QG)
N$94: E6.4(QB) E8.9(D:I)
N$95: E3.5(C:I) E6.5(QC)
N$96: E6.1(A) E6.2(B) E8.13(F:I) E9.13(QH)
N$97: E9.1(A) E9.2(B) E24.9(D:I) E25.13(QH)
N$98: E25.1(A) E25.2(B) E28.3(B:I) E31.13(QH)
N$116: E33.3(A:I1) E33.5(B:I0) E36.6(B:O)
N$141: E15.11(D:I0) E20.14(C:O)
PULSE_LA: T1.1(E) ; also sheet 1
SHIFT_CLOCK: E6.8(CLK) E9.8(CLK) E25.8(CLK) E31.8(CLK) ; also sheet 3
START_ADD\: E7.7(S1) E11.7(S1) E26.7(S1) ; also sheet 1,3
SYSTEM_CLEAR\: E6.9(CLR) E9.9(CLR) E25.9(CLR) E30.1(A:CLR) E30.13(B:CLR) E31.9(CLR) ; also sheet 3
TS1\: E27.4(A:I0) E27.5(A:I1) ; also sheet 1
TS3\: E20.9(C:I0) E20.10(C:I1) ; also sheet 1
VCC [supply]: R1.2 R2.2 R3.2 R4.2 R5.2 R6.2 R7.2 R12.2 R13.2 R14.2 R15.2 R20.2 R21.2 R22.2 R23.2 R28.2 R30.2 ; also sheet 1,3
Unconnected: E21.11(D:I0) E21.12(D:I1) E21.13(D:O)

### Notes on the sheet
- FIELD | DATA

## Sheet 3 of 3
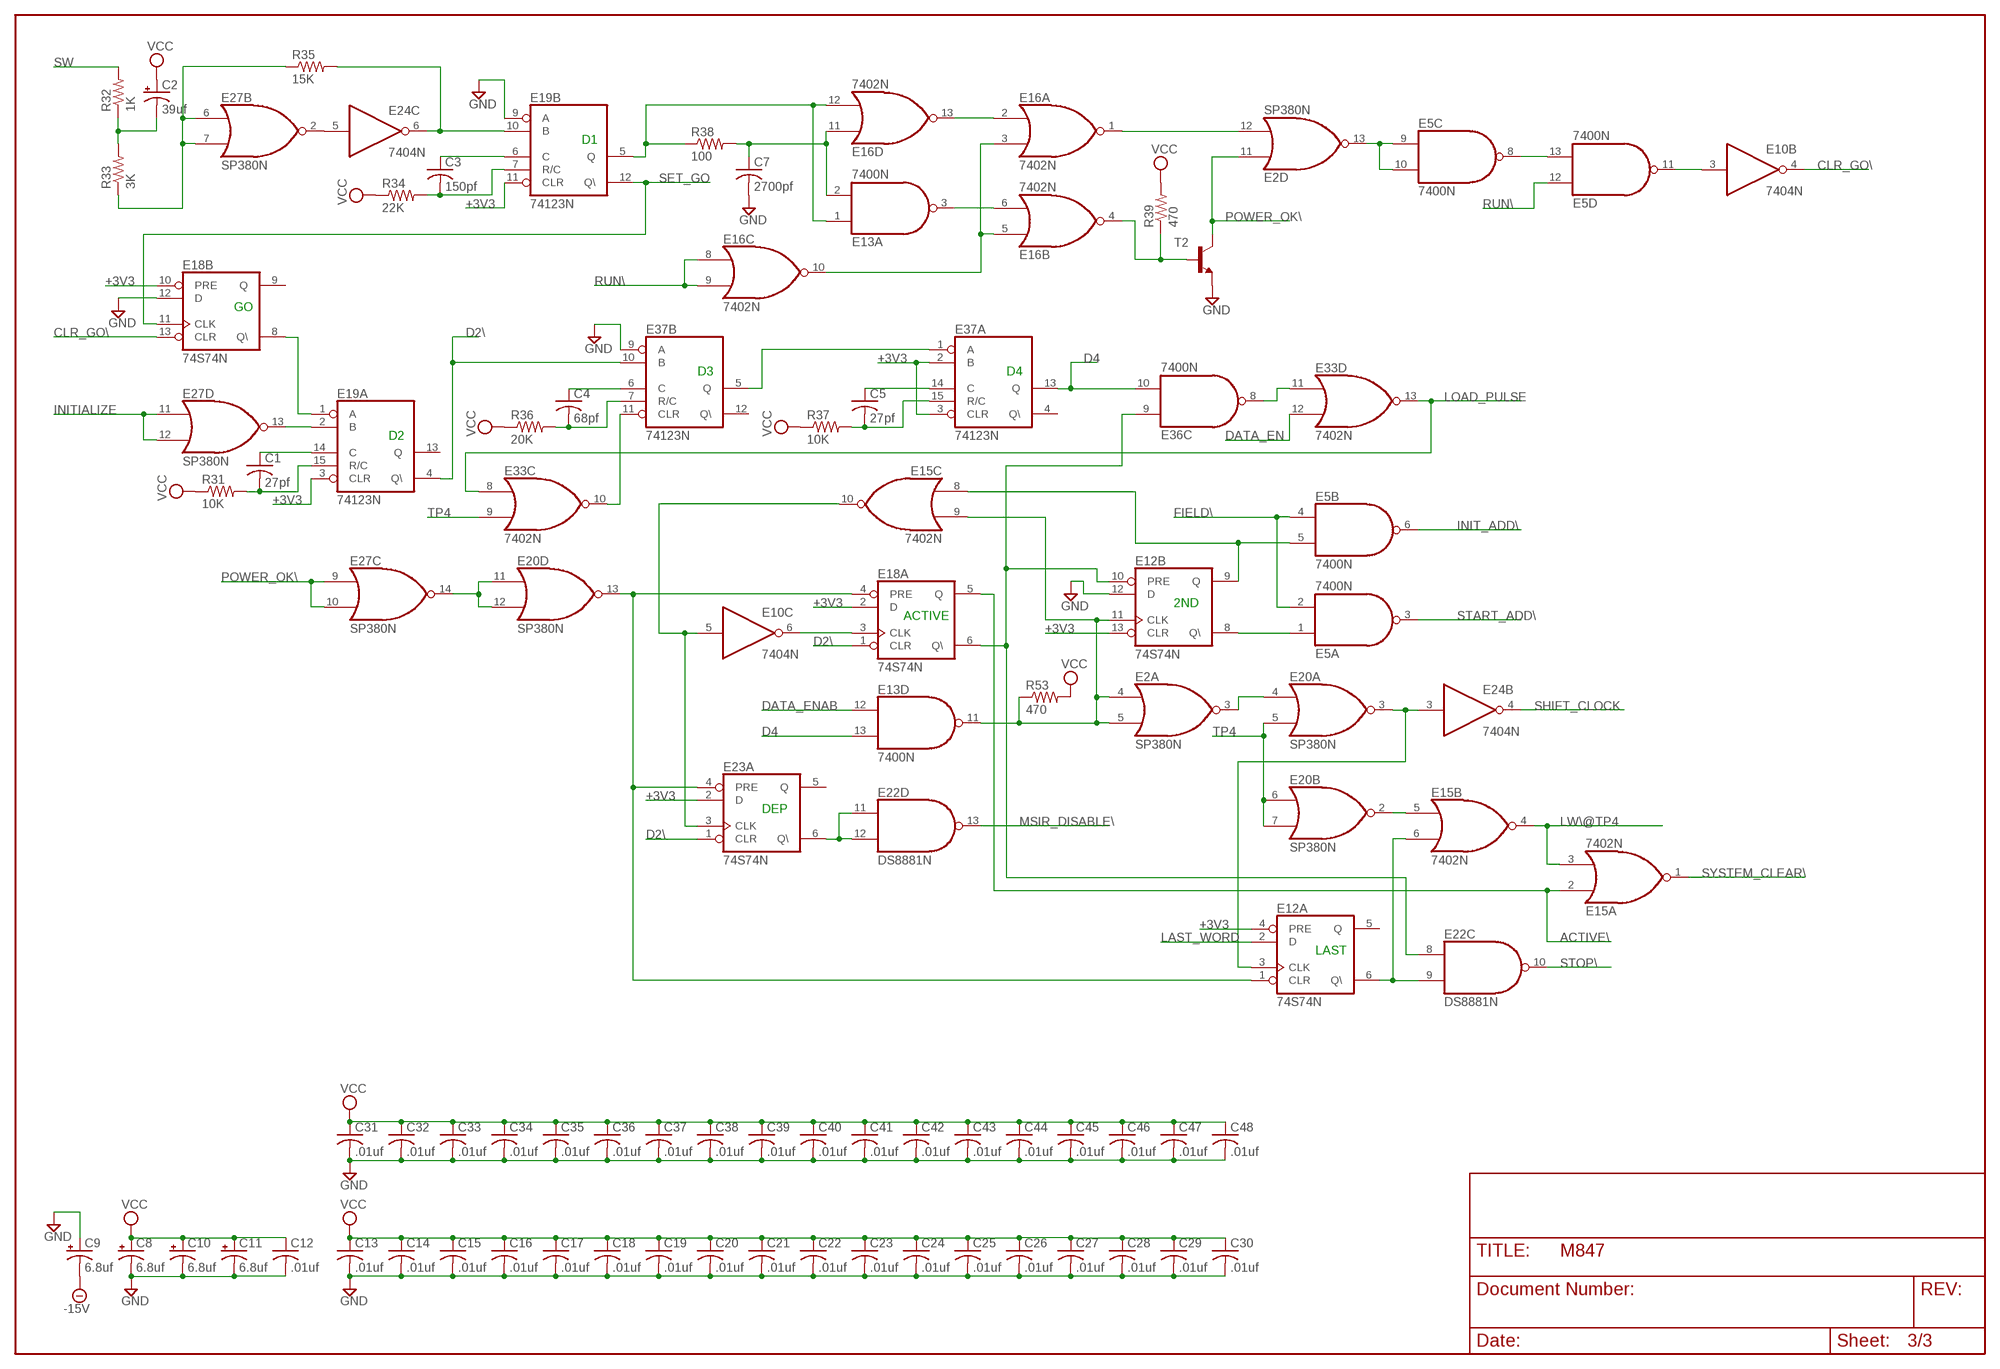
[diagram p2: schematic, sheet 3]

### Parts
C1  27pf  C-US050-025X075  [C050-025X075]
C2  39uf  CPOL-USE15-5AXIAL  [E15-5]
C3  150pf  C-US050-025X075  [C050-025X075]
C4  68pf  C-US050-025X075  [C050-025X075]
C5  27pf  C-US050-025X075  [C050-025X075]
C7  2700pf  C-US102-043X133  [C102-043X133]
C8  6.8uf  CPOL-USE15-5AXIAL  [E15-5]
C9  6.8uf  CPOL-USE15-5AXIAL  [E15-5]
C10  6.8uf  CPOL-USE15-5AXIAL  [E15-5]
C11  6.8uf  CPOL-USE15-5AXIAL  [E15-5]
C12  .01uf  C-US050-025X075  [C050-025X075]
C13  .01uf  C-US050-025X075  [C050-025X075]
C14  .01uf  C-US050-025X075  [C050-025X075]
C15  .01uf  C-US050-025X075  [C050-025X075]
C16  .01uf  C-US050-025X075  [C050-025X075]
C17  .01uf  C-US050-025X075  [C050-025X075]
C18  .01uf  C-US050-025X075  [C050-025X075]
C19  .01uf  C-US050-025X075  [C050-025X075]
C20  .01uf  C-US050-025X075  [C050-025X075]
C21  .01uf  C-US050-025X075  [C050-025X075]
C22  .01uf  C-US050-025X075  [C050-025X075]
C23  .01uf  C-US050-025X075  [C050-025X075]
C24  .01uf  C-US050-025X075  [C050-025X075]
C25  .01uf  C-US050-025X075  [C050-025X075]
C26  .01uf  C-US050-025X075  [C050-025X075]
C27  .01uf  C-US050-025X075  [C050-025X075]
C28  .01uf  C-US050-025X075  [C050-025X075]
C29  .01uf  C-US050-025X075  [C050-025X075]
C30  .01uf  C-US050-025X075  [C050-025X075]
C31  .01uf  C-US050-025X075  [C050-025X075]
C32  .01uf  C-US050-025X075  [C050-025X075]
C33  .01uf  C-US050-025X075  [C050-025X075]
C34  .01uf  C-US050-025X075  [C050-025X075]
C35  .01uf  C-US050-025X075  [C050-025X075]
C36  .01uf  C-US050-025X075  [C050-025X075]
C37  .01uf  C-US050-025X075  [C050-025X075]
C38  .01uf  C-US050-025X075  [C050-025X075]
C39  .01uf  C-US050-025X075  [C050-025X075]
C40  .01uf  C-US050-025X075  [C050-025X075]
C41  .01uf  C-US050-025X075  [C050-025X075]
C42  .01uf  C-US050-025X075  [C050-025X075]
C43  .01uf  C-US050-025X075  [C050-025X075]
C44  .01uf  C-US050-025X075  [C050-025X075]
C45  .01uf  C-US050-025X075  [C050-025X075]
C46  .01uf  C-US050-025X075  [C050-025X075]
C47  .01uf  C-US050-025X075  [C050-025X075]
C48  .01uf  C-US050-025X075  [C050-025X075]
E2  SP380N  [DIL14]
E5  7400N  [DIL14]
E12  74S74N  [DIL14]
E13  7400N  [DIL14]
E16  7402N  [DIL14]
E18  74S74N  [DIL14]
E19  74123N  [DIL16]
E23  74S74N  [DIL14]
E37  74123N  [DIL16]
R31  10K  R-US_0207/10  [0207/10]
R32  1K  R-US_0207/10  [0207/10]
R33  3K  R-US_0207/10  [0207/10]
R34  22K  R-US_0207/10  [0207/10]
R35  15K  R-US_0207/10  [0207/10]
R36  20K  R-US_0207/10  [0207/10]
R37  10K  R-US_0207/10  [0207/10]
R38  100  R-US_0207/10  [0207/10]
R39  470  R-US_0207/10  [0207/10]
R53  470  R-US_0207/10  [0207/10]
T2  -NPN-TO92  [TO92]

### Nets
+3V3 [supply]: E12.4(A:PRE) E12.13(B:CLR) E18.2(A:D) E18.10(B:PRE) E19.3(A:CLR) E19.11(B:CLR) E23.2(A:D) E37.2(A:B) E37.3(A:CLR) ; also sheet 1,2
-15V [supply]: C9.- ; also sheet 1,2
ACTIVE\: E15.2(A:I0) E18.5(A:Q) ; also sheet 2
CLR_GO\: E10.4(B:O) E18.13(B:CLR)
D2\: E18.1(A:CLR) E19.4(A:Q\) E23.1(A:CLR) E37.10(B:B)
D4: E13.13(D:I1) E36.10(C:I1) E37.13(A:Q) ; also sheet 2
DATA_EN: E33.12(D:I1) ; also sheet 2
DATA_ENAB: E13.12(D:I0) ; also sheet 1
FIELD\: E5.2(A:I1) E5.4(B:I0) ; also sheet 2
GND [supply]: C7.2 C8.- C9.+ C10.- C11.- C12.2 C13.2 C14.2 C15.2 C16.2 C17.2 C18.2 C19.2 C20.2 C21.2 C22.2 C23.2 C24.2 C25.2 C26.2 C27.2 C28.2 C29.2 C30.2 C31.2 C32.2 C33.2 C34.2 C35.2 C36.2 C37.2 C38.2 C39.2 C40.2 C41.2 C42.2 C43.2 C44.2 C45.2 C46.2 C47.2 C48.2 E12.12(B:D) E18.12(B:D) E19.9(B:A) E37.9(B:A) T2.1(E) ; also sheet 1,2
INIT_ADD\: E5.6(B:O) ; also sheet 1,2
INITIALIZE: E27.11(D:I0) E27.12(D:I1) ; also sheet 1
LAST_WORD: E12.2(A:D) ; also sheet 2
LOAD_PULSE: E33.8(C:I0) E33.13(D:O) ; also sheet 2
LW\@TP4: E15.3(A:I1) E15.4(B:O)
MSIR_DISABLE\: E22.13(D:O) ; also sheet 1
N$60: E19.2(A:B) E27.13(D:O)
N$61: E10.6(C:O) E18.3(A:CLK)
N$64: E12.6(A:Q\) E15.6(B:I1) E22.9(C:I1)
N$65: C1.1 E19.14(A:C)
N$112: C1.2 E19.15(A:R/C) R31.2
N$113: C3.1 E19.6(B:C)
N$114: C2.- R32.1 R33.2
N$115: E27.6(B:I0) E27.7(B:I1) R33.1 R35.1
N$117: E24.5(C:I) E27.2(B:O)
N$118: E19.10(B:B) E24.6(C:O) R35.2
N$119: C3.2 E19.7(B:R/C) R34.2
N$120: E18.8(B:Q\) E19.1(A:A)
N$121: C4.2 E37.7(B:R/C) R36.2
N$122: C4.1 E37.6(B:C)
N$123: C5.1 E37.14(A:C)
N$124: C5.2 E37.15(A:R/C) R37.2
N$125: E37.1(A:A) E37.5(B:Q)
N$126: E13.1(A:I0) E16.12(D:I1) E19.5(B:Q) R38.1
N$127: C7.1 E13.2(A:I1) E16.11(D:I0) R38.2
N$128: E16.2(A:I0) E16.13(D:O)
N$129: E16.3(A:I1) E16.5(B:I0) E16.10(C:O)
N$130: E13.3(A:O) E16.6(B:I1)
N$131: E2.12(D:I1) E16.1(A:O)
N$132: E2.13(D:O) E5.9(C:I0) E5.10(C:I1)
N$133: E16.4(B:O) R39.1 T2.2(B)
N$134: E5.8(C:O) E5.13(D:I1)
N$135: E12.10(B:PRE) E18.6(A:Q\) E22.8(C:I0) E36.9(C:I0)
N$136: E5.11(D:O) E10.3(B:I)
N$137: E33.11(D:I0) E36.8(C:O)
N$138: E33.10(C:O) E37.11(B:CLR)
N$139: E12.1(A:CLR) E18.4(A:PRE) E20.13(D:O) E23.4(A:PRE)
N$140: E20.11(D:I0) E20.12(D:I1) E27.14(C:O)
N$143: E2.4(A:I0) E2.5(A:I1) E12.11(B:CLK) E13.11(D:O) E15.9(C:I1) R53.1
N$144: E22.11(D:I0) E22.12(D:I1) E23.6(A:Q\)
N$145: E12.3(A:CLK) E20.3(A:O) E24.3(B:I)
N$147: E5.5(B:I1) E12.9(B:Q) E15.8(C:I0)
N$148: E5.1(A:I0) E12.8(B:Q\)
N$149: E15.5(B:I0) E20.2(B:O)
N$151: E2.3(A:O) E20.4(A:I0)
N$152: E10.5(C:I) E15.10(C:O) E23.3(A:CLK)
POWER_OK\: E2.11(D:I0) E27.9(C:I0) E27.10(C:I1) T2.3(C) ; also sheet 1
RUN\: E5.12(D:I0) E16.8(C:I0) E16.9(C:I1) ; also sheet 1
SET_GO: E18.11(B:CLK) E19.12(B:Q\)
SHIFT_CLOCK: E24.4(B:O) ; also sheet 2
START_ADD\: E5.3(A:O) ; also sheet 1,2
STOP\: E22.10(C:O) ; also sheet 1
SW: R32.2 ; also sheet 1
SYSTEM_CLEAR\: E15.1(A:O) ; also sheet 2
TP4: E20.5(A:I1) E20.6(B:I0) E20.7(B:I1) E33.9(C:I1) ; also sheet 1
VCC [supply]: C2.+ C8.+ C10.+ C11.+ C12.1 C13.1 C14.1 C15.1 C16.1 C17.1 C18.1 C19.1 C20.1 C21.1 C22.1 C23.1 C24.1 C25.1 C26.1 C27.1 C28.1 C29.1 C30.1 C31.1 C32.1 C33.1 C34.1 C35.1 C36.1 C37.1 C38.1 C39.1 C40.1 C41.1 C42.1 C43.1 C44.1 C45.1 C46.1 C47.1 C48.1 R31.1 R34.1 R36.1 R37.1 R39.2 R53.2 ; also sheet 1,2
Unconnected: E2.2(B:O) E2.6(B:I0) E2.7(B:I1) E2.9(C:I0) E2.10(C:I1) E2.14(C:O) E12.5(A:Q) E13.4(B:I0) E13.5(B:I1) E13.6(B:O) E13.8(C:O) E13.9(C:I0) E13.10(C:I1) E18.9(B:Q) E19.13(A:Q) E23.5(A:Q) E23.8(B:Q\) E23.9(B:Q) E23.10(B:PRE) E23.11(B:CLK) E23.12(B:D) E23.13(B:CLR) E37.4(A:Q\) E37.12(B:Q\)

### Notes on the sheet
- D1
- GO
- D3 | D4
- D2
- 2ND
- ACTIVE
- DEP
- LAST

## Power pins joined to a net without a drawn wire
GND: E1.1(GND) E2.1(P:GND) E3.7(P:GND) E4.7(P:GND) E5.7(P:GND) E6.7(GND) E7.8(GND) E8.7(P:GND) E9.7(GND) E10.7(P:GND) E11.8(GND) E12.7(P:GND) E13.7(P:GND) E14.7(P:GND) E15.7(P:GND) E16.7(P:GND) E17.1(GND) E18.7(P:GND) E19.8(P:GND) E20.1(P:GND) E21.7(P:GND) E22.7(P:GND) E23.7(P:GND) E24.7(P:GND) E25.7(GND) E26.8(GND) E27.1(P:GND) E28.7(P:GND) E29.7(P:GND) E30.7(P:GND) E31.7(GND) E32.7(P:GND) E33.7(P:GND) E34.7(P:GND) E35.1(GND) E36.7(P:GND) E37.8(P:GND)
VCC: E1.8(VCC) E2.8(P:VCC) E3.14(P:VCC) E4.14(P:VCC) E5.14(P:VCC) E6.14(VCC) E7.16(VCC) E8.14(P:VCC) E9.14(VCC) E10.14(P:VCC) E11.16(VCC) E12.14(P:VCC) E13.14(P:VCC) E14.14(P:VCC) E15.14(P:VCC) E16.14(P:VCC) E17.8(VCC) E18.14(P:VCC) E19.16(P:VCC) E20.8(P:VCC) E21.14(P:VCC) E22.14(P:VCC) E23.14(P:VCC) E24.14(P:VCC) E25.14(VCC) E26.16(VCC) E27.8(P:VCC) E28.14(P:VCC) E29.14(P:VCC) E30.14(P:VCC) E31.14(VCC) E32.14(P:VCC) E33.14(P:VCC) E34.14(P:VCC) E35.8(VCC) E36.14(P:VCC) E37.16(P:VCC)

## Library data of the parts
C1 C3-C7 C12-C48 = rcl:C-US: CAPACITOR, American symbol
C2 C8-C11 = rcl:CPOL-US: POLARIZED CAPACITOR, American symbol
D1-D386 = diode:1N4148: DIODE
E1 E17 E35 = dec-con:SP384: Quad OR gate
E2 E20 E27 = dec-con:SP380: Quad NOR gate (use 8640)
E3 E8 E10 E24 E28 E34 = 74xx-jameco:74*04: Hex INVERTER
E4 E14 E21 E22 E29 E32 = dec-con:DS8881: Quad 2-input NAND gate, open collector
E5 E13 = 74xx-jameco:74*00: Quad 2-input NAND gate
E6 E9 E25 E31 = 74xx-jameco:74*164: 8-bit parallel out SHIFT REGISTER
E7 E11 E26 = dec-con:DEC8235: 4-bit data selector
E12 E18 E23 = 74xx-jameco:74*74: Dual D type positive edge triggered FLIP FLOP, preset and clear
E15 E16 E33 = 74xx-jameco:74*02: Quad 2-input NOR gate
E19 E37 = 74xx-jameco:74*123: Retriggerable monostable MULTIVIBRATOR
E30 = 74xx-us:74*74: Dual D type positive edge triggered FLIP FLOP, preset and clear
E36 = 74xx-us:74*00: Quad 2-input NAND gate
F0 F1 F2 I0 I1-I11 S0 S1-S11 = jumper:J: Bridge
R1-R53 = rcl:R-US_: RESISTOR, American symbol
T1 T2 = transistor:*-NPN-: NPN Transistror
U$1 = dec-con:OUTLINE-*: Board outlines for DEC boards.
U$2 = dec-con:QUAD: Quad-Height DEC board

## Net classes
1 supply: width 0.635 mm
